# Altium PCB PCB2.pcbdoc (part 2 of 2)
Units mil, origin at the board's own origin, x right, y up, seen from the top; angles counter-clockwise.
Board outline 3540 x 3355 mil, 4 copper layers (Top Layer, GND, PWR, Bottom Layer), stack 62.5 mil thick; 130 components, 101 nets, 421 pads, 287 vias.
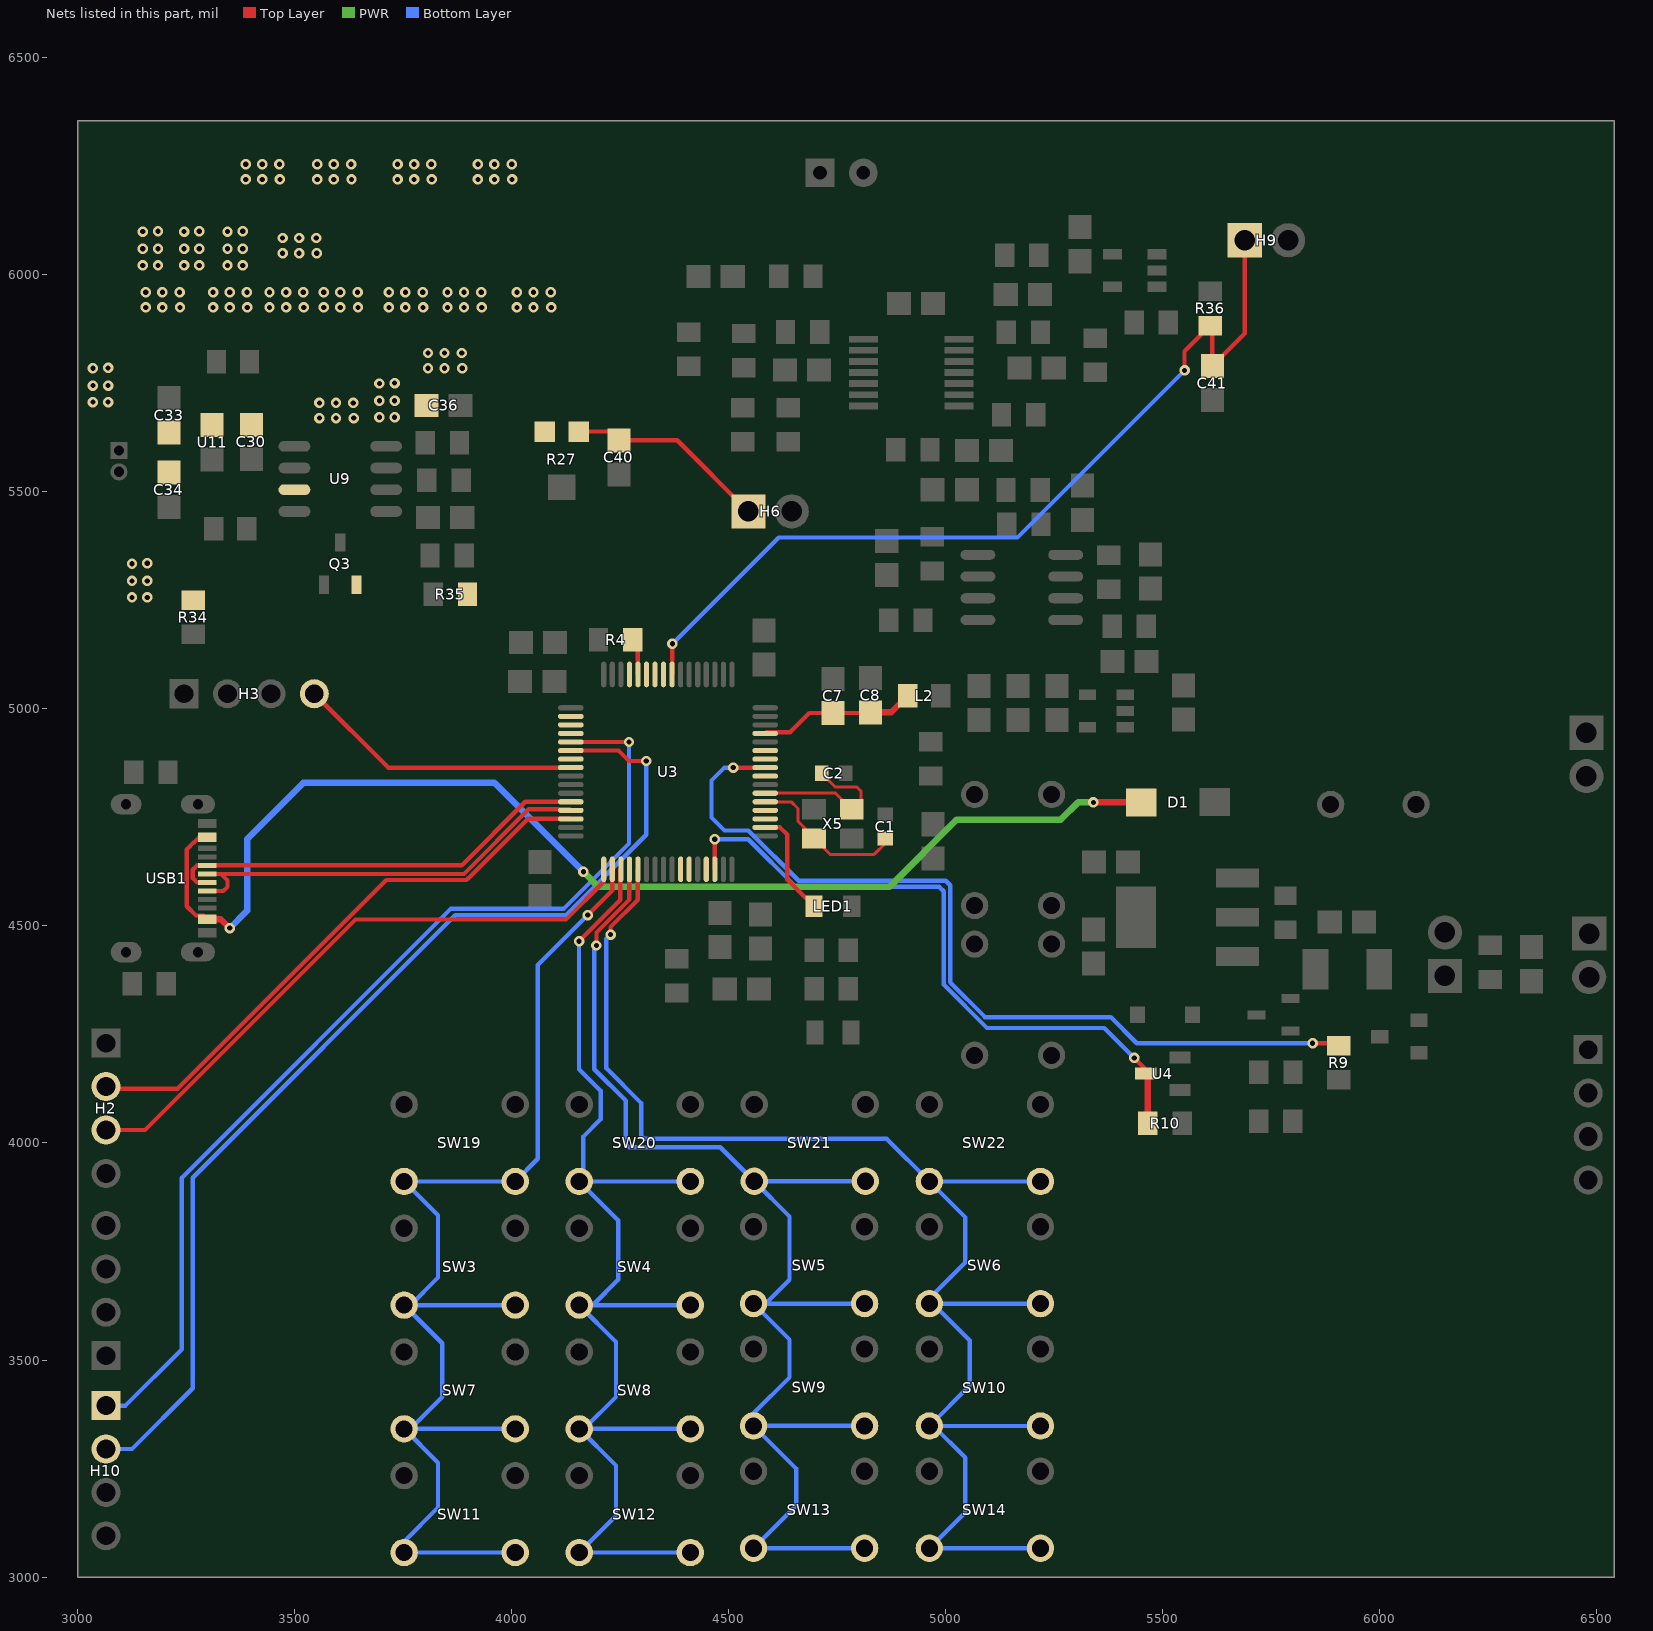
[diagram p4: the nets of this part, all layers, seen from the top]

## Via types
v1: diameter 24, hole 12, Top Layer to Bottom Layer, 287 vias

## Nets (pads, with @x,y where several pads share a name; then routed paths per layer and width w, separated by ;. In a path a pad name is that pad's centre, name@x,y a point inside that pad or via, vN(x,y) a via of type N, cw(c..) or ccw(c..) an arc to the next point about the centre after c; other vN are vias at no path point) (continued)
PA11: U3.44 USB1.A7 USB1.B7 | length 992.9
  Top Layer w10: USB1.A7@3298.5,4600.2 3275,4600.2 3265,4610.2 3265,4629.5 3275,4639.5 USB1.B7@3298.5,4639.5 3884.5,4639.5 4031.1,4786.1 U3.44@4136.1,4786.1
PA12: U3.45 USB1.A6 USB1.B6 | length 987
  Top Layer w10: USB1.B6@3298.5,4580.5 3335.5,4580.5 3345,4590 3345,4605 3330.2,4619.8 ; USB1.A6@3298.5,4619.8 3330.2,4619.8 ; U3.45@4136.1,4766.4 4133.3,4769.2 4039.2,4769.2 3889.8,4619.8 3330.2,4619.8
PA13: H2.2 U3.46 | length 1330.7
  Top Layer w10: H2.2@3065,4130 3070,4125 3230,4125 3710.8,4605.8 3895.7,4605.8 3899.8,4610 3900,4610 4036.7,4746.7 U3.46@4136.1,4746.7
PA14: H2.3 U3.49 | length 1412.5
  Top Layer w10: H2.3@3065,4030 3155,4030 3640,4515 4125,4515 4211.9,4601.9 U3.49@4211.9,4630.6
PA15: SW3.C SW3.D SW7.C SW7.D SW11.C SW11.D SW19.C SW19.D U3.50 | length 2865.8
  Top Layer w10: v1(4175,4525) 4231.6,4581.6 U3.50@4231.6,4630.6
  Bottom Layer w10: SW3.C@3752.1,3626.4 3840,3538.5 3840,3415 SW7.C@3766.4,3341.4 ; SW11.D@4007.9,3056.4 3752.1,3056.4 3752.1,3082.1 3830,3160 3830,3263.5 3752.1,3341.4 SW7.C@3766.4,3341.4 ; SW7.D@4007.9,3341.4 SW7.C@3766.4,3341.4 ; SW3.D@4007.9,3626.4 3766.4,3626.4 3830,3690 3830,3833.5 3752.1,3911.4 4007.9,3911.4 4060,3963.5 4060,4410 v1(4175,4525)
PB0: U3.26
PB1: U3.27
PB2: R4.1 U3.28 | length 85.4
  Top Layer w10: R4.1@4278.4,5159.7 4290.6,5147.5 U3.28@4290.6,5079.4
PB6: U3.58
PB7: U3.59
PB8: U3.61
PB9: R10.1 U3.62 U4.3 | length 1534.4
  Top Layer w10: U3.62@4467.8,4630.6 v1(4467.8,4700) ; v1(5434.1,4195.9) 5460.6,4169.4 U4.3@5460.6,4160
  Top Layer w15: U4.3@5460.6,4160 5465.6,4155 R10.1@5465.6,4045
  Bottom Layer w10: v1(4467.8,4700) 4545,4700 4655,4590 4985,4590 4995,4580 4995,4365 5095,4265 5365,4265 v1(5434.1,4195.9)
PB10: U3.29
PB13: U3.34
PB14: U3.35
PB15: U3.36
PC0: U3.8
PC1: R9.1 U3.9 | length 2015.2
  Top Layer w10: v1(4510,4864.8) U3.9@4583.9,4864.8 ; v1(5845,4230) 5899.4,4230 R9.1@5905,4224.4
  Bottom Layer w10: v1(4510,4864.8) 4489.8,4864.8 4460,4835 4460,4750 4490,4720 4545,4720 4661,4604 5000,4604 5010,4594 5010,4370 5090,4290 5380,4290 5440,4230 v1(5845,4230)
PC2: U3.10
PC3: U3.11
PC4: C41.2 H9.1 R36.2 U3.24 | length 2054.8
  Top Layer w10: U3.24@4369.4,5079.4 4370,5080 v1(4370,5150) ; v1(5550,5780) 5550,5824.2 R36.2@5609,5883.2 5614,5878.2 C41.2@5614,5790.3 5688.6,5864.9 H9.1@5688.6,6079.8
  Bottom Layer w10: v1(4370,5150) 4615,5395 5165,5395 v1(5550,5780)
PC5: U3.25
PC6: H10.1 U3.37 | length 2340.6
  Top Layer w10: U3.37@4136.1,4923.9 v1(4270,4923.9)
  Bottom Layer w10: H10.1@3065,3395 3110,3395 3240,3525 3240,3920 3860,4540 4120,4540 4270,4690 v1(4270,4923.9)
PC7: H10.2 U3.38 | length 2469.1
  Top Layer w10: U3.38@4136.1,4904.2 4245.8,4904.2 4270,4880 v1(4310,4880)
  Bottom Layer w10: H10.2@3065,3295 3125,3295 3265,3435 3265,3920 3870,4525 4125,4525 4310,4710 v1(4310,4880)
PC8: U3.39
PC9: H3.4 U3.40 | length 661.6
  Top Layer w10: H3.4@3545,5035 3715.2,4864.8 U3.40@4136.1,4864.8
PC10: SW4.C SW4.D SW8.C SW8.D SW12.C SW12.D SW20.C SW20.D U3.51 | length 2833.9
  Top Layer w10: v1(4155,4465) 4250,4560 4250,4629.3 U3.51@4251.3,4630.6
  Bottom Layer w10: v1(4155,4465) 4155,4170 4205,4120 4205,4055 4165,4015 4165,3921 SW20.C@4155.4,3911.4 ; SW8.C@4155.4,3341.4 4240,3256.8 4240,3141 SW12.C@4155.4,3056.4 SW12.D@4411.3,3056.4 ; SW4.C@4155.4,3626.4 4240,3541.8 4240,3415 4166.4,3341.4 SW8.D@4411.3,3341.4 ; SW4.D@4411.3,3626.4 4186.4,3626.4 4245,3685 4245,3821.8 SW20.C@4155.4,3911.4 ; SW20.D@4411.3,3911.4 SW20.C@4155.4,3911.4
PC11: SW5.C SW5.D SW9.C SW9.D SW13.C SW13.D SW21.C SW21.D U3.52 | length 3075.3
  Top Layer w10: v1(4195,4455) 4195,4485 4271,4561 U3.52@4271,4630.6
  Bottom Layer w10: v1(4195,4455) 4190,4450 4190,4170 4262.9,4097.1 4262.9,3997.1 4270,3990 4480.5,3990 SW21.C@4558.7,3911.8 ; SW5.C@4557.1,3630 4640,3547 4640,3460 4557.1,3377.1 SW9.C@4557.1,3348.2 ; SW13.D@4812.9,3066.4 4557.1,3066.4 4655,3164.4 4655,3250.2 SW9.C@4557.1,3348.2 ; SW9.D@4812.9,3348.2 SW9.C@4557.1,3348.2 ; SW5.D@4812.9,3630 4585,3630 4640,3685 4640,3830.5 SW21.C@4558.7,3911.8 ; SW21.D@4814.6,3911.8 SW21.C@4558.7,3911.8
PC12: SW6.C SW6.D SW10.C SW10.D SW14.C SW14.D SW22.C SW22.D U3.53 | length 3459.7
  Top Layer w10: v1(4227.6,4480) 4227.6,4497.4 4290.6,4560.5 U3.53@4290.6,4630.6
  Bottom Layer w10: v1(4227.6,4480) 4218,4470.4 4218,4172 4297.9,4092.1 4297.9,4017.1 4305,4010 4863.5,4010 SW22.C@4962.1,3911.4 ; SW14.D@5217.9,3066.4 4962.1,3066.4 5045,3149.4 5045,3275 SW10.C@4971.9,3348.1 ; SW10.D@5217.9,3348.1 SW10.C@4971.9,3348.1 ; SW6.D@5217.9,3629.8 SW6.C@4970.2,3629.8 ; SW22.D@5217.9,3911.4 SW22.C@4962.1,3911.4 ; SW22.C@4962.1,3911.4 5045,3828.5 5045,3725 4962.1,3642.1 4962.1,3629.8 SW6.C@4970.2,3629.8 ; SW6.C@4970.2,3629.8 5055,3545 5055,3441 4962.1,3348.1 SW10.C@4971.9,3348.1
PC13: LED1.1 U3.2 | length 248.7
  Top Layer w10: U3.2@4583.9,4727.1 4617.9,4727.1 4635,4710 4635,4606.7 LED1.1@4696.7,4545
PC14: U3.3
PC15: U3.4
PGND: C30.1 C33.1 C34.2 C36.1 Q3.2 R27.1 R34.2 R35.1 U9.7 U11.1
  other v1: 3125,5256.9 3160,5256.9 3125,5295 3160,5295 3125,5334.7 3160,5335.7 3556.9,5670 3595,5670 3635.7,5670 3695,5671.9 3730,5671.9 3556.9,5705 3595,5705 3634.7,5705 3035,5706.9 3070,5706.9 3695,5710 3730,5710 3035,5745 3070,5745 3695,5749.7 3730,5750.7 3035,5784.7 3806.9,5785 3845,5785 3885.7,5785 3070,5785.7 3806.9,5820 3845,5820 3884.7,5820 3156.9,5925 3195,5925 3235.7,5925 3311.9,5925 3350,5925 3390.7,5925 3441.9,5925 3480,5925 3520.7,5925 3566.9,5925 3605,5925 3645.7,5925 3716.9,5925 3755,5925 3795.7,5925 3851.9,5925 3890,5925 3930.7,5925 4011.9,5925 4050,5925 4090.7,5925 3156.9,5960 3195,5960 3234.7,5960 3311.9,5960 3350,5960 3389.7,5960 3441.9,5960 3480,5960 3519.7,5960 3566.9,5960 3605,5960 3644.7,5960 3716.9,5960 3755,5960 3794.7,5960 3851.9,5960 3890,5960 3929.7,5960 4011.9,5960 4050,5960 4089.7,5960 3150,6021.9 3185,6021.9 3245,6021.9 3280,6021.9 3345,6021.9 3380,6021.9 3471.9,6050 3510,6050 3550.7,6050 3150,6060 3185,6060 3245,6060 3280,6060 3345,6060 3380,6060 3471.9,6085 3510,6085 3549.7,6085 3150,6099.7 3245,6099.7 3345,6099.7 3185,6100.7 3280,6100.7 3380,6100.7 3386.9,6220 3425,6220 3465.7,6220 3551.9,6220 3590,6220 3630.7,6220 3736.9,6220 3775,6220 3815.7,6220 3921.9,6220 3960,6220 4000.7,6220 3386.9,6255 3425,6255 3464.7,6255 3551.9,6255 3590,6255 3629.7,6255 3736.9,6255 3775,6255 3814.7,6255 3921.9,6255 3960,6255 3999.7,6255
PH0: C1.2 U3.5 X5.1 | length 367
  Top Layer w7: U3.5@4583.9,4786.1 4643.9,4786.1 4659.6,4770.4 4659.6,4740.9 4696.7,4703.9 X5.1@4696.7,4701.5 4733.2,4665 4835,4665 4860.8,4690.8 C1.2@4860.8,4701.4
PH1: C2.2 U3.6 X5.3 | length 373.8
  Top Layer w7: U3.6@4583.9,4805.8 4746,4805.8 X5.3@4783.3,4768.5 4805,4790.2 4805,4810 4795,4820 4745,4820 4714.3,4850.7 C2.2@4714.3,4851.6
TX_1: C40.1 H6.1 R27.3 | length 466.8
  Top Layer w10: R27.3@4154.4,5639 4226.8,5639 C40.1@4247,5618.8 4381.2,5618.8 H6.1@4545,5455
VBUS: D1.1 USB1.A4B9 USB1.B4A9 | length 2825.6
  Top Layer w10: USB1.B4A9@3298.5,4515.5 3289.8,4524.2 3272.3,4524.2 3251,4545.5 3251,4676 3268.2,4693.2 3269,4693.2 3280.3,4704.5 USB1.A4B9@3298.5,4704.5
  Top Layer w15: USB1.B4A9@3298.5,4515.5 3329.5,4515.5 v1(3350,4495) ; v1(5340,4784.6) D1.1@5450.4,4784.6
  PWR w15: v1(4165,4625) 4200,4590 4870,4590 5025,4745 5265,4745 5304.6,4784.6 v1(5340,4784.6)
  Bottom Layer w15: v1(3350,4495) 3390,4535 3390,4700 3520,4830 3960,4830 v1(4165,4625)
VREF+: C7.2 C8.2 L2.2 U3.13 | length 363.9
  Top Layer w10: U3.13@4583.9,4943.6 4586.7,4946.4 4641.2,4946.4 4685.5,4990.6 C7.2@4740,4990.6 4824.5,4990.6 C8.2@4826.1,4992.2
  Top Layer w15: C8.2@4826.1,4992.2 4874.2,4992.2 L2.2@4912,5030
pads on no net: U8.4 U9.2 USB1.A8 USB1.B8

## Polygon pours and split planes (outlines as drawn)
PGND on Top Layer (solid, remove dead copper, pour order 4): 3000,6355 4194.4,6355 4194.4,5434.4 3982.8,5222.8 3000,5222.8
agnd on Top Layer (solid, remove dead copper, pour order 8): 4211.5,6355 6540,6355 6540,4897.1 4820.4,4897.1 4794.5,4923 4623,4923 4615,4915 4530,4915 4525,4920 4525,4985 4595,5055 4630,5055 4630,5230 4600,5260 4040,5260 4205,5425 4205,6348.5
GND on Top Layer (solid, remove dead copper, pour order 12): 3000,5190.9 3975.9,5190.9 4030,5245 4595,5245 4615,5225 4615,5070 4585,5070 4510,4995 4510,4921.8 4526.9,4905 4615,4905 4625,4915 4790,4915 4851.8,4865.3 6540,4865.3 6540,3000 3000,3000
PGND on Bottom Layer (solid, remove dead copper, pour order 6): 3000,6355 4194.4,6355 4194.4,5434.4 3982.8,5222.8 3000,5222.8
AGND on Bottom Layer (solid, remove dead copper, pour order 10): 4211.5,6355 6540,6355 6540,4897.1 4820.4,4897.1 4794.5,4923 4623,4923 4615,4915 4530,4915 4525,4920 4525,4985 4595,5055 4630,5055 4630,5230 4600,5260 4040,5260 4205,5425 4205,6348.5
GND on Bottom Layer (solid, remove dead copper, pour order 14): 3000,5190.9 3975.9,5190.9 4030,5245 4595,5245 4615,5225 4615,5070 4585,5070 4510,4995 4510,4921.8 4526.3,4889.1 4615.9,4889.1 4625,4915 4790,4915 4830,4869.8 6540,4869.8 6540,3000 3000,3000
PGND on GND (solid, remove dead copper): 3000,6355 4194.4,6355 4194.4,5434.4 3982.8,5222.8 3000,5222.8
AGND on GND (solid, remove dead copper): 4211.5,6355 6540,6355 6540,4897.1 4820.4,4897.1 4794.5,4923 4623,4923 4615,4915 4530,4915 4525,4920 4525,4985 4595,5055 4630,5055 4630,5230 4600,5260 4040,5260 4205,5425 4205,6348.5
GND on GND (solid, remove dead copper): 3000,5190.9 3975.9,5190.9 4030,5245 4595,5245 4615,5225 4615,5070 4585,5070 4510,4995 4510,4921.8 4531.7,4889.1 4615.9,4889.1 4625,4915 4790,4915 4830.6,4869.9 6540,4869.9 6540,3000 3000,3000

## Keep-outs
Board Outline Layer:
  region: 4545,4815 4660,4815 4675,4830 4670,4835 4670,4880 4685,4895 4805,4895 4810,4890 4810,4830 4820,4820 4860,4820 4904.8,4775.2 4904.8,4645 4665,4645 4645,4655.8 4645,4775 4545,4775
  lines w10: 3000,3000 3000,6355 6540,6355 6540,3000 3000,3000

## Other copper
Top Layer:
  drawing of 480 lines, arcs and shapes, not listed
PWR:
  region net AVCC: 5136.3,5120 5136.3,5110 5134.5,5109.7 5132.3,5108.7 5129.9,5107.5 5127.9,5106 5127.9,5124 5129.9,5122.5 5132.3,5121.3 5134.5,5120.3
  region net AVCC: 5385,5408.7 5375,5408.7 5374.7,5410.5 5373.7,5412.7 5372.5,5415.1 5371,5417.1 5389,5417.1 5387.5,5415.1 5386.3,5412.7 5385.3,5410.5
  region net AVCC: 5375,5441.3 5385,5441.3 5385.3,5439.5 5386.3,5437.3 5387.5,5434.9 5389,5432.9 5371,5432.9 5372.5,5434.9 5373.7,5437.3 5374.7,5439.5
  region net AVCC: 5130.1,5747 5123,5739.9 5121.5,5740.9 5119.3,5741.9 5116.7,5742.6 5114.2,5743 5127,5755.8 5127.4,5753.3 5128.1,5750.7 5129.1,5748.5
  region net AVCC: 5131.3,5760 5131.3,5750 5129.5,5749.7 5127.3,5748.7 5124.9,5747.5 5122.9,5746 5122.9,5764 5124.9,5762.5 5127.3,5761.3 5129.5,5760.3
  region net AVCC: 5340,5958.7 5330,5958.7 5329.7,5960.5 5328.7,5962.7 5327.5,5965.1 5326,5967.1 5344,5967.1 5342.5,5965.1 5341.3,5962.7 5340.3,5960.5
  region net AVCC: 5099.9,5763 5107,5770.1 5108.5,5769.1 5110.7,5768.1 5113.3,5767.4 5115.8,5767 5103,5754.2 5102.6,5756.7 5101.9,5759.3 5100.9,5761.5
  region net AVCC: 4771.3,6000 4771.3,5990 4769.5,5989.7 4767.3,5988.7 4764.9,5987.5 4762.9,5986 4762.9,6004 4764.9,6002.5 4767.3,6001.3 4769.5,6000.3
  region net AVCC: 4747,5979.9 4739.9,5987 4740.9,5988.5 4741.9,5990.7 4742.6,5993.3 4743,5995.8 4755.8,5983 4753.3,5982.6 4750.7,5981.9 4748.5,5980.9
  region net AVCC: 4491.3,5790 4491.3,5780 4489.5,5779.7 4487.3,5778.7 4484.9,5777.5 4482.9,5776 4482.9,5794 4484.9,5792.5 4487.3,5791.3 4489.5,5790.3
  region net 3.3V: 5324.5,4712.5 5324.5,4727.5 5327.1,4727.6 5329.6,4728 5331.7,4728.5 5332.9,4729 5332.9,4711 5331.7,4711.5 5329.6,4712 5327.1,4712.4
  region net 3.3V: 4149.4,4601.2 4138.8,4590.6 4136.8,4592.4 4134.8,4593.9 4133,4595.1 4131.7,4595.5 4144.5,4608.3 4144.9,4607 4146.1,4605.2 4147.6,4603.2
  region net 3.3V: 4116.2,4600 4116.2,4615 4118.8,4615.1 4121.3,4615.5 4123.4,4616 4124.6,4616.5 4124.6,4598.5 4123.4,4599 4121.3,4599.5 4118.8,4599.9
  region net 3.3V: 3121,4237.5 3121,4222.5 3116.6,4222.2 3112.4,4221.2 3108.4,4219.5 3104.7,4217.3 3101.3,4214.5 3098.5,4211.3 3098.5,4248.8 3101.3,4245.5 3104.7,4242.7 3108.4,4240.5 3112.4,4238.8 3116.6,4237.8 3121,4237.5
  region net 3.3V: 3106.4,4199.2 3095.8,4188.6 3091.5,4191.4 3086.9,4193.6 3082.1,4195.2 3077.1,4196.2 3071.9,4196.5 3098.5,4223.1 3098.8,4217.9 3099.8,4212.9 3101.4,4208.1 3103.6,4203.5 3106.4,4199.2
  region net 3.3V: 3100,3517.5 3100,3502.5 3098.9,3496.9 3098.5,3491.3 3098.5,3528.7 3098.9,3523.1
  region net 3.3V: 4125,4623.8 4140,4623.8 4140.1,4621.2 4140.5,4618.7 4141,4616.6 4141.5,4615.4 4123.5,4615.4 4124,4616.6 4124.5,4618.7 4124.9,4621.2
  region net 3.3V: 4193.7,4988.1 4183.1,4998.7 4184.9,5000.7 4186.4,5002.7 4187.6,5004.5 4188,5005.8 4200.8,4993 4199.5,4992.6 4197.7,4991.4 4195.7,4989.9
  region net 3.3V: 5334.6,4703.1 5324,4713.7 5325.7,4715.7 5327.3,4717.7 5328.4,4719.5 5328.9,4720.8 5341.6,4708 5340.4,4707.6 5338.6,4706.4 5336.5,4704.9
  region net 3.3V: 5533.7,3982.5 5533.7,3997.5 5536.3,3997.6 5538.8,3998 5540.9,3998.5 5542.1,3999 5542.1,3981 5540.9,3981.5 5538.8,3982 5536.3,3982.4
  region net 3.3V: 5566.3,3997.5 5566.3,3982.5 5563.7,3982.4 5561.2,3982 5559.1,3981.5 5557.9,3981 5557.9,3999 5559.1,3998.5 5561.2,3998 5563.7,3997.6
  region net 3.3V: 6424,4207.5 6424,4222.5 6428.4,4222.8 6432.6,4223.8 6436.6,4225.5 6440.3,4227.7 6443.7,4230.5 6446.5,4233.8 6446.5,4196.2 6443.7,4199.5 6440.3,4202.3 6436.6,4204.5 6432.6,4206.2 6428.4,4207.2 6424,4207.5
  region net 5V_IN: 5726.5,4689.1 5715.9,4678.5 5714,4680.3 5711.9,4681.8 5710.1,4682.9 5708.9,4683.4 5721.6,4696.1 5722.1,4694.9 5723.2,4693.1 5724.7,4691.1
  region net 5V_IN: 6088.1,4377.5 6088.1,4392.5 6092.5,4392.8 6096.7,4393.8 6100.7,4395.5 6104.4,4397.7 6107.8,4400.5 6110.6,4403.8 6110.6,4366.2 6107.8,4369.5 6104.4,4372.3 6100.7,4374.5 6096.7,4376.2 6092.5,4377.2 6088.1,4377.5
  region net 5V_SYS: 5849.2,4803.2 5863.3,4817.4 5864.7,4816.5 5866.8,4815.6 5869.6,4814.7 5873,4813.8 5876.7,4813 5880.6,4812.3 5884.6,4811.8 5888.5,4811.4 5855.1,4778 5854.8,4782 5854.3,4786 5853.6,4789.9 5852.8,4793.6 5851.9,4797 5851,4799.8 5850.1,4801.9
  region net 5V_SYS: 3570,5525.6 3550,5525.6 3549.9,5527.7 3549.7,5529.9 3549,5533.9 3548.3,5537.3 3548,5540 3572,5540 3571.7,5537.3 3571,5533.9 3570.3,5529.9 3570.1,5527.7
  region net 5V_SYS: 3576.3,5547.5 3576.3,5532.5 3573.7,5532.4 3571.2,5532 3569.1,5531.5 3567.9,5531 3567.9,5549 3569.1,5548.5 3571.2,5548 3573.7,5547.6
  region net 5V_SYS: 3966.3,5371.9 3976.9,5361.3 3975.1,5359.3 3973.6,5357.3 3972.4,5355.5 3972,5354.2 3959.2,5367 3960.5,5367.4 3962.3,5368.6 3964.3,5370.1
  region net VBUS: 5323.7,4777.1 5323.7,4792.1 5326.3,4792.3 5328.8,4792.6 5330.9,4793.1 5332.1,4793.6 5332.1,4775.6 5330.9,4776.2 5328.8,4776.7 5326.3,4777
  region net VBUS: 4181.9,4618.7 4171.3,4608.1 4169.3,4609.9 4167.3,4611.4 4165.5,4612.6 4164.2,4613 4177,4625.8 4177.4,4624.5 4178.6,4622.7 4180.1,4620.7
  region net 3.3V: 3103.8,3478.3 3096.7,3471.2 3093.1,3473.5 3089.2,3475.2 3085,3476.2 3080.8,3476.5 3098.5,3494.2 3098.8,3490 3099.8,3485.8 3101.5,3481.9 3103.8,3478.3
  region net 3.3V: 3109.7,3226.8 3101.8,3204.7 3100.6,3203.4 3099.7,3201.9 3098.9,3200.3 3098.2,3198.6 3097.2,3194.9 3096.6,3191.1 3095.7,3184.1 3095.2,3181.2 3094.8,3180 3094.4,3179 3077.2,3226.2 3081.7,3224.7 3086.4,3223.7 3091.3,3223.1 3096,3223 3100.3,3223.3 3104.2,3224 3105.9,3224.6 3107.4,3225.2 3108.7,3225.9
  region net 3.3V: 4218.8,5008.7 4213.1,4993.7 4210.6,4993.9 4208.3,4994.1 4206.2,4994.2 4205.4,4994.1 4204.7,4994 4210.4,5011.1 4210.8,5010.6 4211.5,5010.2 4213.5,5009.5 4216.1,5008.9
  region net 3.3V: 4533.7,5018.1 4523.1,5028.7 4524.9,5030.7 4526.4,5032.7 4527.6,5034.5 4528,5035.8 4540.8,5023 4539.5,5022.6 4537.7,5021.4 4535.7,5019.9
  region net 3.3V: 3705,4655.6 3704.7,4647.1 3703.7,4638.6 3702,4630.2 3699.7,4622 3696.7,4614 3693.2,4606.3 3689,4598.8 3684.3,4591.7 3679,4585.1 3673.2,4578.8 3683.8,4568.2 3690.1,4574 3696.7,4579.3 3703.8,4584 3711.3,4588.2 3719,4591.7 3727,4594.7 3735.2,4597 3743.6,4598.7 3752.1,4599.7 3760.6,4600 3765,4615 3759.1,4615.4 3753.4,4616.5 3747.8,4618.4 3742.5,4621 3737.6,4624.3 3733.2,4628.2 3729.3,4632.6 3726,4637.5 3723.4,4642.8 3721.5,4648.4 3720.4,4654.1 3720,4660 3705,4655.6
  region net 3.3V: 3352.5,4989.4 3337.5,4989.4 3337.1,4990.5 3336,4992.4 3332,4998.1 3326.4,5005.2 3319.9,5012.9 3370.1,5012.9 3363.6,5005.2 3358,4998.1 3354,4992.4 3352.9,4990.5
Bottom Layer:
  region net PA15: 3785.9,3884.6 3778.8,3877.6 3776.2,3878 3769.6,3878.6 3750.1,3880 3783.5,3913.4 3784.9,3893.9 3785.5,3887.3
  region net PA15: 3790.6,3657.7 3786.9,3639.8 3785.8,3638.6 3785,3637.2 3784.2,3635.6 3783.7,3633.9 3782.9,3630.3 3782.4,3626.6 3782,3619.5 3781.7,3616.6 3781.2,3614.4 3760.3,3656.8 3764.8,3655.8 3769.4,3655.1 3774,3654.8 3778.5,3654.7 3782.5,3655 3786,3655.6 3788.8,3656.5 3789.8,3657.1
  region net PA15: 3785.9,3599.6 3778.8,3592.6 3776.2,3593 3769.6,3593.6 3750.1,3595 3783.5,3628.4 3784.9,3608.9 3785.5,3602.3
  region net PA15: 3790.6,3372.7 3786.9,3354.8 3785.8,3353.6 3785,3352.2 3784.2,3350.6 3783.7,3348.9 3782.9,3345.3 3782.4,3341.6 3782,3334.5 3781.7,3331.6 3781.2,3329.4 3760.3,3371.8 3764.8,3370.8 3769.4,3370.1 3774,3369.8 3778.5,3369.7 3782.5,3370 3786,3370.6 3788.8,3371.5 3789.8,3372.1
  region net PA15: 3785.9,3314.6 3778.8,3307.6 3776.2,3308 3769.6,3308.6 3750.1,3310 3783.5,3343.4 3784.9,3323.9 3785.5,3317.3
  region net PA15: 3753.7,3090.8 3780,3102.9 3778.9,3101.7 3778,3100.3 3777.2,3098.7 3776.5,3097 3776,3095.1 3775.5,3093.1 3775.1,3089 3775.2,3084.7 3775.9,3080.5 3776.4,3078.5 3777.1,3076.5 3777.9,3074.6 3778.9,3072.9 3732.3,3081 3734.1,3082 3736.4,3082.9 3742.1,3084.7 3745.2,3085.7 3748.3,3087 3751.2,3088.7 3752.5,3089.7
  region net PA15: 3794.9,3916.4 3794.9,3906.4 3792.8,3904.8 3787.7,3900.6 3772.9,3887.8 3772.9,3935 3787.7,3922.2 3792.8,3918
  region net PA15: 3965.1,3906.4 3965.1,3916.4 3967.2,3918 3972.3,3922.2 3987.1,3935 3987.1,3887.8 3972.3,3900.6 3967.2,3904.8
  region net PC10: 4198.3,3916.4 4198.3,3906.4 4196.1,3904.8 4191,3900.6 4176.2,3887.8 4176.2,3935 4191,3922.2 4196.1,3918
  region net PC10: 4368.4,3906.4 4368.4,3916.4 4370.6,3918 4375.6,3922.2 4390.5,3935 4390.5,3887.8 4375.6,3900.6 4370.6,3904.8
  region net PA15: 3794.9,3631.4 3794.9,3621.4 3792.8,3619.8 3787.7,3615.6 3772.9,3602.8 3772.9,3650 3787.7,3637.2 3792.8,3633
  region net PA15: 3965.1,3621.4 3965.1,3631.4 3967.2,3633 3972.3,3637.2 3987.1,3650 3987.1,3602.8 3972.3,3615.6 3967.2,3619.8
  region net PA15: 3794.9,3346.4 3794.9,3336.4 3792.8,3334.8 3787.7,3330.6 3772.9,3317.8 3772.9,3365 3787.7,3352.2 3792.8,3348
  region net PA15: 3965.1,3336.4 3965.1,3346.4 3967.2,3348 3972.3,3352.2 3987.1,3365 3987.1,3317.8 3972.3,3330.6 3967.2,3334.8
  region net PA15: 3794.9,3061.4 3794.9,3051.4 3792.8,3049.8 3787.7,3045.6 3772.9,3032.8 3772.9,3080 3787.7,3067.2 3792.8,3063
  region net PA15: 3965.1,3051.4 3965.1,3061.4 3967.2,3063 3972.3,3067.2 3987.1,3080 3987.1,3032.8 3972.3,3045.6 3967.2,3049.8
  region net PC10: 4189.2,3884.6 4182.2,3877.6 4179.5,3878 4172.9,3878.6 4153.4,3880 4186.8,3913.4 4188.2,3893.9 4188.8,3887.3
  region net PC10: 4205.2,3652.3 4190,3622.9 4187.6,3620.3 4185.6,3617.4 4183.7,3614.6 4182.1,3611.7 4179.2,3606.6 4177.9,3604.6 4176.6,3603.1 4176.2,3650.1 4177.6,3649 4179.2,3648.1 4180.9,3647.3 4182.7,3646.7 4184.6,3646.3 4186.5,3646.1 4188.6,3646 4190.6,3646.1 4192.6,3646.3 4194.7,3646.7 4196.6,3647.2 4198.5,3647.9 4200.4,3648.8 4202.1,3649.8 4203.7,3650.9
  region net PC10: 4198.3,3631.4 4198.3,3621.4 4196.1,3619.8 4191,3615.6 4176.2,3602.8 4176.2,3650 4191,3637.2 4196.1,3633
  region net PC10: 4368.4,3621.4 4368.4,3631.4 4370.6,3633 4375.6,3637.2 4390.5,3650 4390.5,3602.8 4375.6,3615.6 4370.6,3619.8
  region net PC10: 4189.2,3599.6 4182.2,3592.6 4179.5,3593 4172.9,3593.6 4153.4,3595 4186.8,3628.4 4188.2,3608.9 4188.8,3602.3
  region net PC10: 4191.4,3373.4 4190.2,3358.1 4189.1,3356.8 4188.2,3355.4 4187.5,3353.8 4187,3352.1 4186.3,3348.3 4186,3344.5 4185.9,3337.1 4185.8,3334.1 4185.3,3331.7 4161.3,3372.4 4165.9,3371.6 4170.7,3371.2 4175.4,3370.9 4179.8,3371 4183.8,3371.2 4187.2,3371.7 4189.8,3372.5 4190.7,3372.9
  region net PC10: 4198.3,3346.4 4198.3,3336.4 4196.1,3334.8 4191,3330.6 4176.2,3317.8 4176.2,3365 4191,3352.2 4196.1,3348
  region net PC10: 4368.4,3336.4 4368.4,3346.4 4370.6,3348 4375.6,3352.2 4390.5,3365 4390.5,3317.8 4375.6,3330.6 4370.6,3334.8
  region net PC10: 4189.2,3314.6 4182.2,3307.6 4179.5,3308 4172.9,3308.6 4153.4,3310 4186.8,3343.4 4188.2,3323.9 4188.8,3317.3
  region net PC10: 4182.2,3090.3 4189.2,3083.2 4188.8,3080.5 4188.2,3074 4186.8,3054.4 4153.4,3087.9 4172.9,3089.3 4179.5,3089.9
  region net PC10: 4198.3,3061.4 4198.3,3051.4 4196.1,3049.8 4191,3045.6 4176.2,3032.8 4176.2,3080 4191,3067.2 4196.1,3063
  region net PC10: 4368.4,3051.4 4368.4,3061.4 4370.6,3063 4375.6,3067.2 4390.5,3080 4390.5,3032.8 4375.6,3045.6 4370.6,3049.8
  region net PA15: 4034.7,3945.3 4041.8,3938.2 4041.4,3935.5 4040.8,3929 4039.4,3909.4 4006,3942.9 4025.5,3944.3 4032.1,3944.9
  region net PA15: 4167,4509.9 4159.9,4517 4160.9,4518.5 4161.9,4520.7 4162.6,4523.3 4163,4525.8 4175.8,4513 4173.3,4512.6 4170.7,4511.9 4168.5,4510.9
  region net PC11: 4601.6,3916.8 4601.6,3906.8 4599.4,3905.2 4594.4,3900.9 4579.5,3888.1 4579.5,3935.4 4594.4,3922.6 4599.4,3918.4
  region net PC11: 4771.7,3906.8 4771.7,3916.8 4773.9,3918.4 4779,3922.6 4793.8,3935.4 4793.8,3888.1 4779,3900.9 4773.9,3905.2
  region net PC11: 4592.6,3885 4585.5,3877.9 4582.8,3878.3 4576.3,3878.9 4556.7,3880.3 4590.2,3913.7 4591.6,3894.2 4592.2,3887.6
  region net PC11: 4605.1,3657.2 4591.1,3629.1 4589,3626.5 4587.3,3623.7 4585.8,3620.8 4584.5,3617.8 4582.4,3612.5 4581.4,3610.3 4580.3,3608.7 4575.9,3655.2 4577.4,3654.2 4579.1,3653.4 4580.9,3652.7 4582.8,3652.1 4584.7,3651.7 4586.8,3651.5 4590.9,3651.5 4592.9,3651.7 4594.9,3652 4596.9,3652.5 4598.8,3653.2 4600.6,3654 4602.2,3654.9 4603.7,3656
  region net PC11: 4599.9,3635 4599.9,3625 4597.8,3623.4 4592.7,3619.2 4577.9,3606.4 4577.9,3653.6 4592.7,3640.8 4597.8,3636.6
  region net PC11: 4770.1,3625 4770.1,3635 4772.2,3636.6 4777.3,3640.8 4792.1,3653.6 4792.1,3606.4 4777.3,3619.2 4772.2,3623.4
  region net PC11: 4590.9,3603.2 4583.8,3596.1 4581.2,3596.5 4574.6,3597.1 4555.1,3598.5 4588.5,3631.9 4589.9,3612.4 4590.5,3605.8
  region net PC11: 4555.1,3382.2 4583.9,3396.8 4582.6,3395.4 4581.5,3393.8 4580.6,3392.2 4579.8,3390.4 4579.1,3388.5 4578.6,3386.5 4578.2,3384.5 4578,3382.4 4577.9,3380.4 4578,3378.4 4578.3,3376.3 4578.7,3374.4 4579.2,3372.5 4579.9,3370.8 4580.8,3369.1 4581.9,3367.6 4535.2,3370.9 4536.7,3372 4538.8,3373.1 4544,3375.4 4546.9,3376.7 4549.8,3378.2 4552.6,3380
  region net PC11: 4599.9,3353.2 4599.9,3343.2 4597.8,3341.6 4592.7,3337.4 4577.9,3324.6 4577.9,3371.8 4592.7,3359 4597.8,3354.8
  region net PC11: 4770.1,3343.2 4770.1,3353.2 4772.2,3354.8 4777.3,3359 4792.1,3371.8 4792.1,3324.6 4777.3,3337.4 4772.2,3341.6
  region net PC11: 4590.9,3321.4 4583.8,3314.3 4581.2,3314.7 4574.6,3315.3 4555.1,3316.8 4588.5,3350.2 4589.9,3330.6 4590.5,3324.1
  region net PC11: 4583.8,3100.3 4590.9,3093.2 4590.5,3090.5 4589.9,3084 4588.5,3064.4 4555.1,3097.9 4574.6,3099.3 4581.2,3099.9
  region net PC11: 4599.9,3071.4 4599.9,3061.4 4597.8,3059.8 4592.7,3055.6 4577.9,3042.8 4577.9,3090 4592.7,3077.2 4597.8,3073
  region net PC11: 4770.1,3061.4 4770.1,3071.4 4772.2,3073 4777.3,3077.2 4792.1,3090 4792.1,3042.8 4777.3,3055.6 4772.2,3059.8
  region net PC11: 4524.9,3938.5 4531.9,3945.6 4534.6,3945.2 4541.2,3944.6 4560.7,3943.2 4527.3,3909.8 4525.9,3929.3 4525.3,3935.9
  region net PC11: 4195,4435.6 4185,4443.1 4184.9,4444.8 4184.5,4447 4183.5,4451.5 4199.9,4444 4199,4443.5 4198.1,4442.7 4197.3,4441.7 4196.5,4440.6 4195.9,4439.4 4195.4,4438.1 4195.1,4436.8
  region net PC10: 4160,3960.5 4170,3946.1 4170.1,3944.4 4170.5,3942.8 4171.1,3941.2 4171.9,3939.6 4174,3936.5 4176.3,3933.6 4181.1,3928.3 4183,3926 4184.2,3924 4139.3,3938.5 4143.1,3941 4146.9,3943.8 4150.4,3946.9 4153.5,3950 4156.2,3953 4158.2,3955.9 4159.5,3958.4 4159.9,3959.5
  region net PC10: 4160,4448.7 4150,4448.7 4149.7,4450.5 4148.7,4452.7 4147.5,4455.1 4146,4457.1 4164,4457.1 4162.5,4455.1 4161.3,4452.7 4160.3,4450.5
  region net PC12: 5004.9,3916.4 5004.9,3906.4 5002.8,3904.8 4997.7,3900.6 4982.9,3887.8 4982.9,3935 4997.7,3922.2 5002.8,3918
  region net PC12: 5175.1,3906.4 5175.1,3916.4 5177.2,3918 5182.3,3922.2 5197.1,3935 5197.1,3887.8 5182.3,3900.6 5177.2,3904.8
  region net PC12: 4995.9,3884.6 4988.8,3877.6 4986.2,3878 4979.6,3878.6 4960.1,3880 4993.5,3913.4 4994.9,3893.9 4995.5,3887.3
  region net PC12: 4977.5,3664.6 4993.8,3666.7 4993.2,3666 4992.7,3665 4991.9,3662.4 4991.4,3659 4991.1,3654.9 4991.1,3650.5 4991.4,3645.9 4992,3641.1 4992.8,3636.5 4951.5,3659.4 4953.8,3659.9 4956.8,3660.1 4964,3660.3 4967.8,3660.7 4971.5,3661.4 4973.2,3661.9 4974.8,3662.6 4976.2,3663.5
  region net PC12: 4996.7,3610.4 4995.8,3597.2 4995.2,3597.6 4994.4,3597.9 4991.9,3598.5 4988.7,3599 4984.8,3599.3 4980.3,3599.3 4975.6,3599.3 4970.7,3599 4965.9,3598.5 4992.6,3637.5 4992.9,3635 4992.9,3631.9 4992.8,3624.3 4993,3620.3 4993.6,3616.5 4994.1,3614.8 4994.8,3613.1 4995.6,3611.7
  region net PC12: 4988.8,3381.9 4995.9,3374.9 4995.5,3372.2 4994.9,3365.6 4993.5,3346.1 4960.1,3379.5 4979.6,3380.9 4986.2,3381.5
  region net PC12: 5004.9,3634.8 5004.9,3624.8 5002.8,3623.2 4997.7,3618.9 4982.9,3606.1 4982.9,3653.4 4997.7,3640.6 5002.8,3636.4
  region net PC12: 5175.1,3624.8 5175.1,3634.8 5177.2,3636.4 5182.3,3640.6 5197.1,3653.4 5197.1,3606.1 5182.3,3618.9 5177.2,3623.2
  region net PC12: 4996.8,3330.3 4997.1,3315.8 4996.5,3316.3 4995.6,3316.7 4993.1,3317.4 4989.7,3317.9 4985.8,3318.1 4981.4,3318.2 4976.6,3318 4971.8,3317.6 4967.1,3317 4992.3,3357 4992.6,3354.6 4992.7,3351.5 4992.8,3344 4993,3340.1 4993.7,3336.4 4994.2,3334.6 4994.9,3333 4995.7,3331.6
  region net PC12: 4988.8,3100.3 4995.9,3093.2 4995.5,3090.5 4994.9,3084 4993.5,3064.4 4960.1,3097.9 4979.6,3099.3 4986.2,3099.9
  region net PC12: 5004.9,3353.1 5004.9,3343.1 5002.8,3341.5 4997.7,3337.3 4982.9,3324.5 4982.9,3371.7 4997.7,3358.9 5002.8,3354.7
  region net PC12: 5175.1,3343.1 5175.1,3353.1 5177.2,3354.7 5182.3,3358.9 5197.1,3371.7 5197.1,3324.5 5182.3,3337.3 5177.2,3341.5
  region net PC12: 5004.9,3071.4 5004.9,3061.4 5002.8,3059.8 4997.7,3055.6 4982.9,3042.8 4982.9,3090 4997.7,3077.2 5002.8,3073
  region net PC12: 5175.1,3061.4 5175.1,3071.4 5177.2,3073 5182.3,3077.2 5197.1,3090 5197.1,3042.8 5182.3,3055.6 5177.2,3059.8
  region net PC12: 4928.2,3938.2 4935.3,3945.3 4937.9,3944.9 4944.5,3944.3 4964,3942.9 4930.6,3909.4 4929.2,3929 4928.6,3935.5
  region net PC12: 4221.5,4466.9 4214.5,4473.9 4214.8,4474.7 4215.1,4476.4 4215.6,4480.8 4228.3,4468 4223.9,4467.5 4222.3,4467.2
  region net PC4: 4378,5165.1 4385.1,5158 4384.1,5156.5 4383.1,5154.3 4382.4,5151.7 4382,5149.2 4369.2,5162 4371.7,5162.4 4374.3,5163.1 4376.5,5164.1
  region net PC4: 5542,5764.9 5534.9,5772 5535.9,5773.5 5536.9,5775.7 5537.6,5778.3 5538,5780.8 5550.8,5768 5548.3,5767.6 5545.7,5766.9 5543.5,5765.9
  region net PA9: 3937,4784.9 3929.9,4792 3930.9,4793.5 3931.9,4795.7 3932.6,4798.3 3933,4800.8 3945.8,4788 3943.3,4787.6 3940.7,4786.9 3938.5,4785.9
  region net PA9: 3093.7,3845.8 3100.8,3838.7 3100.4,3835.9 3099.8,3828.9 3098.4,3807.9 3062.9,3843.4 3083.9,3844.8 3090.9,3845.4
  region net PA10: 3947,4739.9 3939.9,4747 3940.9,4748.5 3941.9,4750.7 3942.6,4753.3 3943,4755.8 3955.8,4743 3953.3,4742.6 3950.7,4741.9 3948.5,4740.9
  region net PA10: 3093.7,3745.8 3100.8,3738.7 3100.4,3735.9 3099.8,3728.9 3098.4,3707.9 3062.9,3743.4 3083.9,3744.8 3090.9,3745.4
  region net $1N313: 4750.1,5357 4743,5349.9 4741.5,5350.9 4739.3,5351.9 4736.7,5352.6 4734.2,5353 4747,5365.8 4747.4,5363.3 4748.1,5360.7 4749.1,5358.5
  region net $1N313: 5173.7,5300 5173.7,5310 5175.5,5310.3 5177.7,5311.3 5180.1,5312.5 5182.1,5314 5182.1,5296 5180.1,5297.5 5177.7,5298.7 5175.5,5299.7
  region net $1N237: 6245,4329.4 6265,4329.4 6265.1,4327.3 6265.3,4325.1 6266,4321.1 6266.7,4317.7 6267,4315 6243,4315 6243.3,4317.7 6244,4321.1 6244.7,4325.1 6244.9,4327.3
  region net $1N237: 6265,4510.6 6245,4510.6 6244.9,4512.7 6244.7,4514.9 6244,4518.9 6243.3,4522.3 6243,4525 6267,4525 6266.7,4522.3 6266,4518.9 6265.3,4514.9 6265.1,4512.7
  region net PB9: 5419,4204 5426,4211 5427.6,4210 5429.8,4209 5432.4,4208.3 5434.8,4207.9 5422.1,4195.2 5421.7,4197.6 5421,4200.2 5420,4202.4
  region net $1N237: 5921.3,4337.5 5921.3,4322.5 5918.7,4322.4 5916.2,4322 5914.1,4321.5 5912.9,4321 5912.9,4339 5914.1,4338.5 5916.2,4338 5918.7,4337.6
  region net $1N237: 6238.1,4321.3 6248.7,4331.9 6250.7,4330.1 6252.7,4328.6 6254.5,4327.4 6255.8,4327 6243,4314.2 6242.6,4315.5 6241.4,4317.3 6239.9,4319.3
  region net PC1: 5828.7,4225 5828.7,4235 5830.5,4235.3 5832.7,4236.3 5835.1,4237.5 5837.1,4239 5837.1,4221 5835.1,4222.5 5832.7,4223.7 5830.5,4224.7
  region net PC1: 4493.7,4859.8 4493.7,4869.8 4495.5,4870.2 4497.7,4871.1 4500.1,4872.4 4502.1,4873.8 4502.1,4855.8 4500.1,4857.3 4497.7,4858.6 4495.5,4859.5
  region net PA2: 6444.2,4143.7 6451.3,4150.8 6454.1,4150.4 6461.1,4149.8 6482.1,4148.4 6446.6,4112.9 6445.2,4133.9 6444.6,4140.9
  region net PA3: 6444.2,4043.7 6451.3,4050.8 6454.1,4050.4 6461.1,4049.8 6482.1,4048.4 6446.6,4012.9 6445.2,4033.9 6444.6,4040.9
  region net PA2: 4656.3,5005 4656.3,4995 4654.5,4994.7 4652.3,4993.7 4649.9,4992.5 4647.9,4991 4647.9,5009 4649.9,5007.5 4652.3,5006.3 4654.5,5005.3
  region net PA3: 4506.3,4980.8 4506.3,4970.8 4504.5,4970.4 4502.3,4969.5 4499.9,4968.2 4497.9,4966.7 4497.9,4984.8 4499.9,4983.3 4502.3,4982 4504.5,4981.1
  region net VBUS: 3356.3,4511.9 3366.9,4501.3 3365.1,4499.3 3363.6,4497.3 3362.4,4495.5 3362,4494.2 3349.2,4507 3350.5,4507.4 3352.3,4508.6 3354.3,4510.1
  region net PC7: 3110.6,3300 3110.6,3290 3108.4,3288.3 3103,3283.7 3087.1,3269.9 3087.1,3320.1 3103,3306.3 3108.4,3301.7
  region net VBUS: 4148.1,4631.3 4158.7,4641.9 4160.7,4640.1 4162.7,4638.6 4164.5,4637.4 4165.8,4637 4153,4624.2 4152.6,4625.5 4151.4,4627.3 4149.9,4629.3
  region net PC6: 4275,4907.6 4265,4907.6 4264.7,4909.4 4263.7,4911.6 4262.5,4914 4261,4916 4279,4916 4277.5,4914 4276.3,4911.6 4275.3,4909.4
  region net PC7: 4315,4863.7 4305,4863.7 4304.7,4865.5 4303.7,4867.7 4302.5,4870.1 4301,4872.1 4319,4872.1 4317.5,4870.1 4316.3,4867.7 4315.3,4865.5
  region net PC6: 3110,3400 3110,3390 3107.1,3389.7 3104.4,3388.7 3101.9,3387.1 3099.9,3385 3098.5,3382.5 3098.5,3407.5 3099.9,3405 3101.9,3402.9 3104.4,3401.3 3107.1,3400.3
  region net PB9: 4484.2,4705 4484.2,4695 4482.3,4694.7 4480.1,4693.7 4477.7,4692.5 4475.7,4691 4475.7,4709 4477.7,4707.5 4480.1,4706.3 4482.3,4705.3
  region net GND: 4640,4341.3 4650,4341.3 4650.3,4339.5 4651.3,4337.3 4652.5,4334.9 4654,4332.9 4636,4332.9 4637.5,4334.9 4638.7,4337.3 4639.7,4339.5
  region net GND: 4645.1,4447 4638,4439.9 4636.5,4440.9 4634.3,4441.9 4631.7,4442.6 4629.2,4443 4642,4455.8 4642.4,4453.3 4643.1,4450.7 4644.1,4448.5
  region net GND: 4205,5188.7 4195,5188.7 4194.7,5190.5 4193.7,5192.7 4192.5,5195.1 4191,5197.1 4209,5197.1 4207.5,5195.1 4206.3,5192.7 4205.3,5190.5
  region net GND: 4214.9,5038 4222,5045.1 4223.5,5044.1 4225.7,5043.1 4228.3,5042.4 4230.8,5042 4218,5029.2 4217.6,5031.7 4216.9,5034.3 4215.9,5036.5
  region net PA0: 5171.3,5260 5171.3,5250 5169.5,5249.7 5167.3,5248.7 5164.9,5247.5 5162.9,5246 5162.9,5264 5164.9,5262.5 5167.3,5261.3 5169.5,5260.3
  region net PA0: 6431.2,4982.7 6438.3,4989.8 6441.9,4987.5 6445.8,4985.8 6449.9,4984.8 6454.2,4984.5 6436.5,4966.8 6436.2,4971 6435.2,4975.2 6433.5,4979.1 6431.2,4982.7
  region net AGND: 4655,5908.7 4645,5908.7 4644.7,5910.5 4643.7,5912.7 4642.5,5915.1 4641,5917.1 4659,5917.1 4657.5,5915.1 4656.3,5912.7 4655.3,5910.5
  region net AGND: 4694.9,5733 4702,5740.1 4703.5,5739.1 4705.7,5738.1 4708.3,5737.4 4710.8,5737 4698,5724.2 4697.6,5726.7 4696.9,5729.3 4695.9,5731.5

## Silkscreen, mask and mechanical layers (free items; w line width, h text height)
Top Silkscreen Layer:
  text "RX_ADC" at 5865,6050 h40
  text "PC4" at 5653.6,5976.2 h40
  text "AGND" at 5755,5975 h40
  text "SPK+" at 3085,5825 h60 r270
  text "SPK-" at 3035,5440 h60 r270
  text "TX AOUT" at 4300,5435 h40
  text "SIG" at 4513.1,5345 h40
  text "AGND" at 4605,5345 h40
  text "TX_PWM" at 6355,4955 h40 r90
  text "GND" at 3210,4935 h40
  text "3.3V" at 3310,4935 h40
  text "SCL" at 3425,4935 h40
  text "SDA" at 3520,4935 h40
  text "PA0" at 6405,4910 h40 r90
  text "RST" at 5185,4810 h40 r90
  text "GND" at 6410,4805 h40 r90
  text "PWR_JP" at 6180,4710 h40 r270
  text "5V" at 6430,4455 h40 r90
  text "GND" at 6425,4330 h40 r90
  text "3.3V" at 3130,4255 h40 r270
  text "3.3V" at 6420,4175 h40 r90
  text "DIO" at 3130,4150 h40 r270
  text "PWR" at 5165,4130 h40 r90
  text "TX2" at 6420,4085 h40 r90
  text "CLK" at 3135,4065 h40 r270
  text "RX2" at 6415,3985 h40 r90
  text "GND" at 3135,3965 h40 r270
  text "GND" at 6415,3875 h40 r90
  text "TX1" at 3135,3847.3 h40 r270
  text "RX1" at 3135,3740 h40 r270
  text "GND" at 3135,3645 h40 r270
  text "3.3V" at 3135,3560 h40 r270
  text "TX6" at 3140,3430 h40 r270
  text "RX6" at 3140,3330 h40 r270
  text "3.3V" at 3140,3230 h40 r270
  text "GND" at 3135,3120 h40 r270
